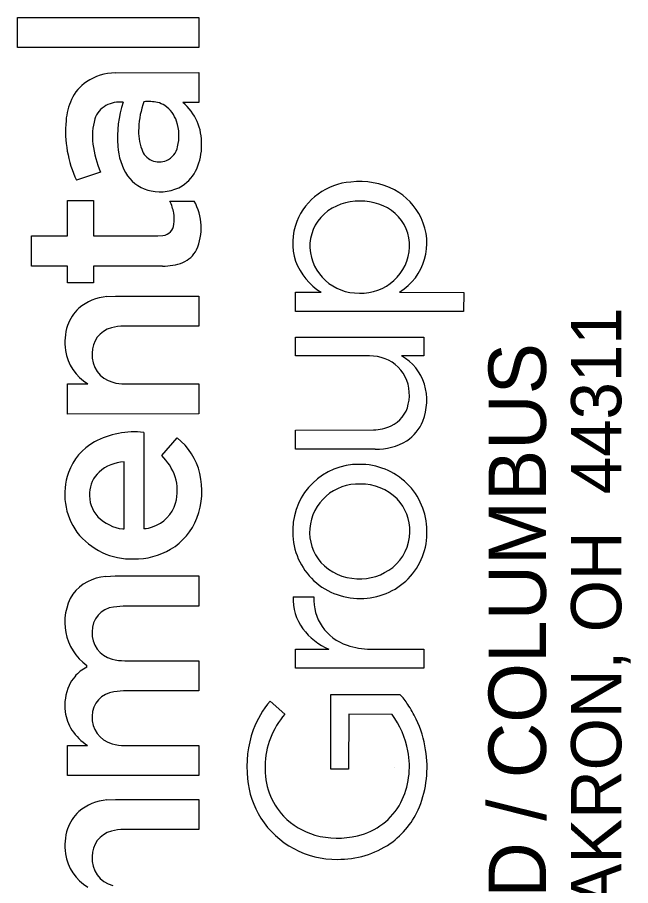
# Model space of a CAD drawing. Extents: x -1 to 34, y 0 to 22.
# Drawn here: x 32.376 to 32.984, y 3.882 to 4.744 of the extents above; entities that cross this region are included whole.
import ezdxf

# ---------------------------------------------------------------- set-up
doc = ezdxf.new("R2010")
doc.units = 0
doc.layers.add('SH_Data', color=7, linetype='Continuous')

msp = doc.modelspace()

# ---------------------------------------------------------------- linework, layer by layer
at = {"layer": 'SH_Data'}
for p, q in [((32.37557, 4.71411), (32.37557, 4.74397)), ((32.37557, 4.74397), (32.55571, 4.74397)), ((32.55571, 4.74397), (32.55571, 4.71411)), ((32.55571, 4.71411), (32.37557, 4.71411)), ((32.47265, 4.68899), (32.55553, 4.68918)), ((32.55553, 4.68918), (32.55571, 4.65956)), ((32.55571, 4.65956), (32.53971, 4.65956)), ((32.45818, 4.59045), (32.43431, 4.58233)), ((32.42542, 4.52705), (32.42548, 4.56209)), ((32.42548, 4.56209), (32.45108, 4.56209)), ((32.45108, 4.56209), (32.45117, 4.52705)), ((32.52695, 4.56159), (32.5511, 4.56159)), ((32.38964, 4.52701), (32.42542, 4.52705)), ((32.38964, 4.49719), (32.38964, 4.52701)), ((32.45117, 4.52705), (32.51498, 4.52705)), ((32.51498, 4.52705), (32.52005, 4.52749)), ((32.42542, 4.49717), (32.38964, 4.49719)), ((32.42542, 4.48067), (32.42542, 4.49717)), ((32.51969, 4.49718), (32.45108, 4.49715)), ((32.45108, 4.49715), (32.45108, 4.48066)), ((32.45108, 4.48066), (32.42542, 4.48067)), ((32.46439, 4.46686), (32.47289, 4.46732)), ((32.47289, 4.46732), (32.55571, 4.46732)), ((32.55571, 4.46732), (32.55571, 4.43753)), ((32.65152, 4.47113), (32.67709, 4.47115)), ((32.65152, 4.45215), (32.65152, 4.47113)), ((32.75491, 4.47132), (32.81858, 4.47108)), ((32.81858, 4.47108), (32.81843, 4.45215)), ((32.81843, 4.45215), (32.65152, 4.45215)), ((32.55571, 4.43753), (32.4814, 4.43746)), ((32.65152, 4.40801), (32.65153, 4.42672)), ((32.65153, 4.42672), (32.7791, 4.42664)), ((32.7791, 4.42664), (32.77908, 4.40796)), ((32.7249, 4.40796), (32.65152, 4.40801)), ((32.7328, 4.40727), (32.7249, 4.40796)), ((32.77908, 4.40796), (32.75689, 4.40796)), ((32.42542, 4.38016), (32.44552, 4.38021)), ((32.42542, 4.35035), (32.42542, 4.38016)), ((32.48222, 4.38021), (32.55569, 4.38021)), ((32.55569, 4.38021), (32.55571, 4.35045)), ((32.55571, 4.35045), (32.42542, 4.35035)), ((32.65154, 4.33443), (32.72905, 4.3345)), ((32.65165, 4.31543), (32.65154, 4.33443)), ((32.50108, 4.33209), (32.50118, 4.23657)), ((32.51882, 4.30927), (32.53422, 4.32662)), ((32.73073, 4.31543), (32.65165, 4.31543)), ((32.48144, 4.23644), (32.48144, 4.30296)), ((32.48016, 4.23628), (32.48144, 4.23644)), ((32.46329, 4.18915), (32.47259, 4.18968)), ((32.47259, 4.18968), (32.55557, 4.18968)), ((32.55557, 4.18968), (32.55571, 4.15982)), ((32.64932, 4.16907), (32.66978, 4.16907)), ((32.48058, 4.15981), (32.47102, 4.15881)), ((32.55571, 4.15982), (32.48058, 4.15981)), ((32.65152, 4.11699), (32.68476, 4.117)), ((32.65152, 4.098), (32.65152, 4.11699)), ((32.72605, 4.11703), (32.7791, 4.11696)), ((32.7791, 4.11696), (32.77903, 4.098)), ((32.48218, 4.10553), (32.55571, 4.10548)), ((32.55571, 4.10548), (32.55571, 4.07568)), ((32.44443, 4.09922), (32.44455, 4.10072)), ((32.77903, 4.098), (32.65152, 4.098)), ((32.4809, 4.07567), (32.47143, 4.07474)), ((32.55571, 4.07568), (32.4809, 4.07567)), ((32.6868, 4.07185), (32.75516, 4.07192)), ((32.6868, 3.99778), (32.6868, 4.07185)), ((32.62636, 4.06548), (32.64114, 4.05241)), ((32.70448, 4.05241), (32.70432, 3.99775)), ((32.74737, 4.05227), (32.70448, 4.05241)), ((32.42542, 3.99152), (32.42545, 4.02138)), ((32.42545, 4.02138), (32.44515, 4.02138)), ((32.48206, 4.02138), (32.55571, 4.02136)), ((32.55571, 4.02136), (32.55571, 3.99156)), ((32.75, 4), (32.75, 4)), ((32.55571, 3.99156), (32.42542, 3.99152)), ((32.70432, 3.99775), (32.6868, 3.99778)), ((32.46439, 3.96736), (32.47289, 3.96783)), ((32.47289, 3.96783), (32.55571, 3.96783)), ((32.55571, 3.96783), (32.55571, 3.93804)), ((32.55571, 3.93804), (32.4814, 3.93796))]:
    msp.add_line(p, q, dxfattribs=at)
msp.add_lwpolyline([(32.37557, 4.71411), (32.37557, 4.74397), (32.55571, 4.74397), (32.55571, 4.71411)], close=True, dxfattribs=at)
for points in [[(32.47265, 4.68899), (32.55553, 4.68918), (32.55571, 4.65956)], [(32.55571, 4.65956), (32.53971, 4.65956)], [(32.45818, 4.59045), (32.43431, 4.58233)], [(32.51969, 4.49718), (32.45108, 4.49715), (32.45108, 4.48066), (32.42542, 4.48067), (32.42542, 4.49717), (32.38964, 4.49719), (32.38964, 4.52701), (32.42542, 4.52705), (32.42548, 4.56209), (32.45108, 4.56209), (32.45117, 4.52705), (32.51498, 4.52705), (32.52005, 4.52749)], [(32.52695, 4.56159), (32.5511, 4.56159)], [(32.46439, 4.46686), (32.47289, 4.46732), (32.55571, 4.46732), (32.55571, 4.43753), (32.4814, 4.43746)], [(32.75491, 4.47132), (32.81858, 4.47108), (32.81843, 4.45215), (32.65152, 4.45215)], [(32.65152, 4.45215), (32.65152, 4.47113), (32.67709, 4.47115)], [(32.7328, 4.40727), (32.7249, 4.40796), (32.65152, 4.40801), (32.65153, 4.42672), (32.7791, 4.42664), (32.77908, 4.40796), (32.75689, 4.40796)], [(32.42542, 4.35035), (32.42542, 4.38016), (32.44552, 4.38021)], [(32.48222, 4.38021), (32.55569, 4.38021), (32.55571, 4.35045), (32.42542, 4.35035)], [(32.73073, 4.31543), (32.65165, 4.31543), (32.65154, 4.33443), (32.72905, 4.3345)], [(32.50108, 4.33209), (32.50118, 4.23657)], [(32.51882, 4.30927), (32.53422, 4.32662)], [(32.48016, 4.23628), (32.48144, 4.23644), (32.48144, 4.30296)], [(32.46329, 4.18915), (32.47259, 4.18968), (32.55557, 4.18968), (32.55571, 4.15982), (32.48058, 4.15981), (32.47102, 4.15881)], [(32.64932, 4.16907), (32.66978, 4.16907)], [(32.72605, 4.11703), (32.7791, 4.11696), (32.77903, 4.098), (32.65152, 4.098)], [(32.65152, 4.098), (32.65152, 4.11699), (32.68476, 4.117)], [(32.48218, 4.10553), (32.55571, 4.10548), (32.55571, 4.07568), (32.4809, 4.07567), (32.47143, 4.07474)], [(32.44443, 4.09922), (32.44455, 4.10072)], [(32.74737, 4.05227), (32.70448, 4.05241), (32.70432, 3.99775), (32.6868, 3.99778), (32.6868, 4.07185), (32.75516, 4.07192)], [(32.62636, 4.06548), (32.64114, 4.05241)], [(32.42542, 3.99152), (32.42545, 4.02138), (32.44515, 4.02138)], [(32.48206, 4.02138), (32.55571, 4.02136), (32.55571, 3.99156), (32.42542, 3.99152)], [(32.46439, 3.96736), (32.47289, 3.96783), (32.55571, 3.96783), (32.55571, 3.93804), (32.4814, 3.93796)]]:
    msp.add_lwpolyline(points, dxfattribs=at)
for centre, radius, start, end in [((32.47452, 4.63256), 0.05646, 91.89422, 122.63175), ((32.47452, 4.63256), 0.05646, 91.89422, 122.63175), ((32.46847, 4.64467), 0.04302, 124.53704, 155.65938), ((32.46847, 4.64467), 0.04302, 124.53704, 155.65938), ((32.48824, 4.63612), 0.06457, 155.9764, 175.31491), ((32.48824, 4.63612), 0.06457, 155.9764, 175.31491), ((32.47525, 4.6356), 0.024, 119.42515, 161.66285), ((32.47525, 4.6356), 0.024, 119.42515, 161.66285), ((32.47786, 4.62778), 0.03213, 85.38017, 116.62224), ((32.47786, 4.62778), 0.03213, 85.38017, 116.62224), ((32.58787, 4.62508), 0.1129, 162.08213, 184.52847), ((32.58787, 4.62508), 0.1129, 162.08213, 184.52847), ((32.58013, 4.63131), 0.08411, 159.83657, 178.03621), ((32.58013, 4.63131), 0.08411, 159.83657, 178.03621), ((32.50509, 4.60743), 0.05302, 79.66963, 94.23216), ((32.50509, 4.60743), 0.05302, 79.66963, 94.23216), ((32.50892, 4.63643), 0.02384, 56.89129, 76.21489), ((32.50892, 4.63643), 0.02384, 56.89129, 76.21489), ((32.5052, 4.63184), 0.02973, 17.59837, 55.72819), ((32.5052, 4.63184), 0.02973, 17.59837, 55.72819), ((32.50551, 4.61914), 0.05295, 358.07459, 49.76196), ((32.50551, 4.61914), 0.05295, 358.07459, 49.76196), ((32.53639, 4.63078), 0.113, 174.61011, 205.38987), ((32.53639, 4.63078), 0.113, 174.61011, 205.38987), ((32.50758, 4.62645), 0.05758, 163.13694, 188.16749), ((32.50758, 4.62645), 0.05758, 163.13694, 188.16749), ((32.4916, 4.6264), 0.04435, 345.94084, 18.99188), ((32.4916, 4.6264), 0.04435, 345.94084, 18.99188), ((32.54655, 4.6303), 0.05063, 175.59026, 199.88569), ((32.54655, 4.6303), 0.05063, 175.59026, 199.88569), ((32.54725, 4.62973), 0.09735, 186.75982, 203.79807), ((32.54725, 4.62973), 0.09735, 186.75982, 203.79807), ((32.53279, 4.61874), 0.05752, 182.56764, 213.71437), ((32.53279, 4.61874), 0.05752, 182.56764, 213.71437), ((32.51642, 4.61886), 0.01841, 198.28436, 293.30806), ((32.51642, 4.61886), 0.01841, 198.28436, 293.30806), ((32.51521, 4.61994), 0.01989, 295.28829, 347.46387), ((32.51521, 4.61994), 0.01989, 295.28829, 347.46387), ((32.50187, 4.61678), 0.05657, 336.01604, 0.59505), ((32.50187, 4.61678), 0.05657, 336.01604, 0.59505), ((32.51752, 4.60969), 0.03938, 303.44357, 336.18), ((32.51752, 4.60969), 0.03938, 303.44357, 336.18), ((32.51487, 4.60782), 0.03656, 215.06685, 259.81327), ((32.51487, 4.60782), 0.03656, 215.06685, 259.81327), ((32.51753, 4.6131), 0.04227, 257.52557, 300.88195), ((32.51753, 4.6131), 0.04227, 257.52557, 300.88195), ((32.71081, 4.51825), 0.06243, 93.98662, 158.31194), ((32.71081, 4.51825), 0.06243, 93.98662, 158.31194), ((32.71557, 4.5065), 0.07459, 62.68889, 97.01346), ((32.71557, 4.5065), 0.07459, 62.68889, 97.01346), ((32.72123, 4.51914), 0.06076, 25.06574, 61.96022), ((32.72123, 4.51914), 0.06076, 25.06574, 61.96022), ((32.48625, 4.54199), 0.04518, 10.15449, 25.72303), ((32.48625, 4.54199), 0.04518, 10.15449, 25.72303), ((32.50302, 4.53506), 0.05491, 336.58903, 28.89913), ((32.50302, 4.53506), 0.05491, 336.58903, 28.89913), ((32.71379, 4.51017), 0.05134, 87.89653, 131.18123), ((32.71379, 4.51017), 0.05134, 87.89653, 131.18123), ((32.7175, 4.51023), 0.05127, 49.90886, 92.03625), ((32.7175, 4.51023), 0.05127, 49.90886, 92.03625), ((32.49573, 4.54365), 0.03556, 351.91398, 10.20594), ((32.49573, 4.54365), 0.03556, 351.91398, 10.20594), ((32.70695, 4.52016), 0.05815, 158.65601, 198.17101), ((32.70695, 4.52016), 0.05815, 158.65601, 198.17101), ((32.7092, 4.51674), 0.04338, 132.32887, 182.09489), ((32.7092, 4.51674), 0.04338, 132.32887, 182.09489), ((32.72154, 4.51733), 0.04327, 358.04871, 47.94467), ((32.72154, 4.51733), 0.04327, 358.04871, 47.94467), ((32.7245, 4.52004), 0.05743, 301.97764, 25.64176), ((32.7245, 4.52004), 0.05743, 301.97764, 25.64176), ((32.51837, 4.54001), 0.01263, 277.61423, 353.79181), ((32.51837, 4.54001), 0.01263, 277.61423, 353.79181), ((32.71352, 4.51815), 0.04776, 183.59741, 271.7045), ((32.71352, 4.51815), 0.04776, 183.59741, 271.7045), ((32.71717, 4.51801), 0.04766, 267.31494, 357.4019), ((32.71717, 4.51801), 0.04766, 267.31494, 357.4019), ((32.52913, 4.52612), 0.02749, 292.68889, 332.05977), ((32.52913, 4.52612), 0.02749, 292.68889, 332.05977), ((32.52088, 4.54856), 0.05139, 268.67266, 291.52354), ((32.52088, 4.54856), 0.05139, 268.67266, 291.52354), ((32.7103, 4.52433), 0.0627, 200.83985, 238.01619), ((32.7103, 4.52433), 0.0627, 200.83985, 238.01619), ((32.46871, 4.41716), 0.04988, 94.97056, 130.22484), ((32.46871, 4.41716), 0.04988, 94.97056, 130.22484), ((32.46348, 4.42551), 0.04016, 132.22383, 161.68229), ((32.46348, 4.42551), 0.04016, 132.22383, 161.68229), ((32.47872, 4.42108), 0.05602, 162.27398, 187.79173), ((32.47872, 4.42108), 0.05602, 162.27398, 187.79173), ((32.48108, 4.39145), 0.04601, 89.60515, 105.33026), ((32.48108, 4.39145), 0.04601, 89.60515, 105.33026), ((32.47482, 4.41155), 0.02498, 103.68683, 182.21395), ((32.47482, 4.41155), 0.02498, 103.68683, 182.21395), ((32.47027, 4.4209), 0.04763, 188.96462, 238.69865), ((32.47027, 4.4209), 0.04763, 188.96462, 238.69865), ((32.47735, 4.40846), 0.02757, 175.58441, 255.13816), ((32.47735, 4.40846), 0.02757, 175.58441, 255.13816), ((32.72711, 4.36998), 0.03772, 33.50082, 81.32954), ((32.72711, 4.36998), 0.03772, 33.50082, 81.32954), ((32.73239, 4.36485), 0.04959, 17.62209, 60.38974), ((32.73239, 4.36485), 0.04959, 17.62209, 60.38974), ((32.72414, 4.3695), 0.04048, 346.56179, 31.75389), ((32.72414, 4.3695), 0.04048, 346.56179, 31.75389), ((32.48183, 4.42235), 0.04215, 254.08913, 270.52838), ((32.48183, 4.42235), 0.04215, 254.08913, 270.52838), ((32.72343, 4.36415), 0.05838, 339.16197, 15.61485), ((32.72343, 4.36415), 0.05838, 339.16197, 15.61485), ((32.73371, 4.36616), 0.03042, 294.63214, 348.48625), ((32.73371, 4.36616), 0.03042, 294.63214, 348.48625), ((32.739, 4.35901), 0.04201, 303.10391, 338.15613), ((32.739, 4.35901), 0.04201, 303.10391, 338.15613), ((32.72747, 4.38081), 0.04633, 271.95199, 294.08943), ((32.72747, 4.38081), 0.04633, 271.95199, 294.08943), ((32.49176, 4.24874), 0.08387, 83.62118, 118.28448), ((32.49176, 4.24874), 0.08387, 83.62118, 118.28448), ((32.49399, 4.2763), 0.06443, 13.53275, 51.36266), ((32.49399, 4.2763), 0.06443, 13.53275, 51.36266), ((32.47894, 4.27368), 0.05583, 118.82935, 160.62242), ((32.47894, 4.27368), 0.05583, 118.82935, 160.62242), ((32.7321, 4.37256), 0.05715, 268.62699, 301.47779), ((32.7321, 4.37256), 0.05715, 268.62699, 301.47779), ((32.48033, 4.27018), 0.05485, 19.0387, 45.44322), ((32.48033, 4.27018), 0.05485, 19.0387, 45.44322), ((32.4844, 4.26071), 0.04236, 94.01311, 130.88062), ((32.4844, 4.26071), 0.04236, 94.01311, 130.88062), ((32.71435, 4.23484), 0.06552, 89.48213, 178.77752), ((32.71435, 4.23484), 0.06552, 89.48213, 178.77752), ((32.71582, 4.23414), 0.06623, 0.42265, 90.7613), ((32.71582, 4.23414), 0.06623, 0.42265, 90.7613), ((32.48697, 4.27074), 0.06438, 160.52138, 215.78155), ((32.48697, 4.27074), 0.06438, 160.52138, 215.78155), ((32.47703, 4.2709), 0.02985, 132.98553, 177.1802), ((32.47703, 4.2709), 0.02985, 132.98553, 177.1802), ((32.48289, 4.27384), 0.0758, 339.35431, 13.37708), ((32.48289, 4.27384), 0.0758, 339.35431, 13.37708), ((32.48724, 4.27433), 0.04701, 344.60723, 17.00675), ((32.48724, 4.27433), 0.04701, 344.60723, 17.00675), ((32.71397, 4.23244), 0.04846, 87.68827, 175.01696), ((32.71397, 4.23244), 0.04846, 87.68827, 175.01696), ((32.71659, 4.23036), 0.05052, 44.91202, 90.75914), ((32.71659, 4.23036), 0.05052, 44.91202, 90.75914), ((32.47824, 4.26966), 0.03114, 175.00138, 223.2876), ((32.47824, 4.26966), 0.03114, 175.00138, 223.2876), ((32.71955, 4.23452), 0.04549, 358.32279, 43.83486), ((32.71955, 4.23452), 0.04549, 358.32279, 43.83486), ((32.49895, 4.27177), 0.03504, 288.01084, 343.55364), ((32.49895, 4.27177), 0.03504, 288.01084, 343.55364), ((32.48546, 4.27826), 0.04232, 225.06454, 262.79701), ((32.48546, 4.27826), 0.04232, 225.06454, 262.79701), ((32.49548, 4.26982), 0.0626, 300.94393, 338.73223), ((32.49548, 4.26982), 0.0626, 300.94393, 338.73223), ((32.48908, 4.27516), 0.06872, 217.74341, 271.65606), ((32.48908, 4.27516), 0.06872, 217.74341, 271.65606), ((32.50129, 4.25678), 0.02021, 269.70042, 294.87295), ((32.50129, 4.25678), 0.02021, 269.70042, 294.87295), ((32.71483, 4.2334), 0.06606, 177.53728, 270.94524), ((32.71483, 4.2334), 0.06606, 177.53728, 270.94524), ((32.71085, 4.23311), 0.0453, 175.51467, 221.42047), ((32.71085, 4.23311), 0.0453, 175.51467, 221.42047), ((32.71671, 4.23271), 0.06536, 269.30834, 1.67905), ((32.71671, 4.23271), 0.06536, 269.30834, 1.67905), ((32.71931, 4.23374), 0.04572, 308.90382, 359.30947), ((32.71931, 4.23374), 0.04572, 308.90382, 359.30947), ((32.49204, 4.27702), 0.07055, 269.20529, 300.33566), ((32.49204, 4.27702), 0.07055, 269.20529, 300.33566), ((32.71399, 4.23734), 0.05046, 222.66255, 268.37331), ((32.71399, 4.23734), 0.05046, 222.66255, 268.37331), ((32.71567, 4.23859), 0.05178, 266.55312, 308.67253), ((32.71567, 4.23859), 0.05178, 266.55312, 308.67253), ((32.46638, 4.14404), 0.04521, 93.91118, 142.30723), ((32.46638, 4.14404), 0.04521, 93.91118, 142.30723), ((32.47585, 4.14373), 0.05319, 148.28793, 233.9556), ((32.47585, 4.14373), 0.05319, 148.28793, 233.9556), ((32.69878, 4.16662), 0.04952, 177.16211, 216.28024), ((32.69878, 4.16662), 0.04952, 177.16211, 216.28024), ((32.71735, 4.16638), 0.04764, 176.76988, 252.15044), ((32.71735, 4.16638), 0.04764, 176.76988, 252.15044), ((32.47384, 4.13499), 0.02399, 96.75763, 181.6251), ((32.47384, 4.13499), 0.02399, 96.75763, 181.6251), ((32.70975, 4.17555), 0.06366, 216.91526, 246.88619), ((32.70975, 4.17555), 0.06366, 216.91526, 246.88619), ((32.47577, 4.13241), 0.02597, 175.81573, 256.16716), ((32.47577, 4.13241), 0.02597, 175.81573, 256.16716), ((32.7269, 4.19175), 0.07473, 251.13884, 269.34694), ((32.7269, 4.19175), 0.07473, 251.13884, 269.34694), ((32.4817, 4.15053), 0.04501, 254.34629, 270.61033), ((32.4817, 4.15053), 0.04501, 254.34629, 270.61033), ((32.4638, 4.06267), 0.04137, 117.91625, 139.24296), ((32.4638, 4.06267), 0.04137, 117.91625, 139.24296), ((32.46194, 4.06452), 0.03875, 139.52447, 154.84698), ((32.46194, 4.06452), 0.03875, 139.52447, 154.84698), ((32.47144, 4.0612), 0.04877, 156.06382, 187.3493), ((32.47144, 4.0612), 0.04877, 156.06382, 187.3493), ((32.47421, 4.05056), 0.02434, 96.5532, 179.94902), ((32.47421, 4.05056), 0.02434, 96.5532, 179.94902), ((32.72498, 4.03937), 0.04438, 30.98913, 47.16099), ((32.72498, 4.03937), 0.04438, 30.98913, 47.16099), ((32.70163, 4.00187), 0.09855, 139.79476, 159.13696), ((32.70163, 4.00187), 0.09855, 139.79476, 159.13696), ((32.67091, 4.00018), 0.11106, 25.30315, 33.96179), ((32.67091, 4.00018), 0.11106, 25.30315, 33.96179), ((32.46461, 4.05974), 0.04181, 186.5579, 213.38846), ((32.46461, 4.05974), 0.04181, 186.5579, 213.38846), ((32.47608, 4.04863), 0.02628, 175.722, 255.78627), ((32.47608, 4.04863), 0.02628, 175.722, 255.78627), ((32.69899, 4.00079), 0.07753, 138.25804, 179.70064), ((32.69899, 4.00079), 0.07753, 138.25804, 179.70064), ((32.67889, 4.00099), 0.08556, 10.07509, 36.83189), ((32.67889, 4.00099), 0.08556, 10.07509, 36.83189), ((32.6704, 3.99987), 0.11166, 8.80339, 25.33484), ((32.6704, 3.99987), 0.11166, 8.80339, 25.33484), ((32.47886, 4.07078), 0.0598, 214.70433, 235.68724), ((32.47886, 4.07078), 0.0598, 214.70433, 235.68724), ((32.7187, 3.99968), 0.11536, 161.14379, 185.62812), ((32.7187, 3.99968), 0.11536, 161.14379, 185.62812), ((32.48195, 4.06518), 0.0438, 253.66719, 270.14979), ((32.48195, 4.06518), 0.0438, 253.66719, 270.14979), ((32.68425, 4.00057), 0.08036, 333.46689, 11.03668), ((32.68425, 4.00057), 0.08036, 333.46689, 11.03668), ((32.67564, 3.99977), 0.10649, 338.28866, 9.28548), ((32.67564, 3.99977), 0.10649, 338.28866, 9.28548), ((32.68811, 3.99732), 0.06676, 176.66577, 223.6912), ((32.68811, 3.99732), 0.06676, 176.66577, 223.6912), ((32.69336, 3.99699), 0.08987, 185.50773, 212.01294), ((32.69336, 3.99699), 0.08987, 185.50773, 212.01294), ((32.46871, 3.91767), 0.04988, 94.97056, 130.22484), ((32.46871, 3.91767), 0.04988, 94.97056, 130.22484), ((32.69868, 3.99547), 0.0652, 282.88151, 331.81475), ((32.69868, 3.99547), 0.0652, 282.88151, 331.81475), ((32.46348, 3.92602), 0.04016, 132.22383, 161.68229), ((32.46348, 3.92602), 0.04016, 132.22383, 161.68229), ((32.69835, 3.99168), 0.08241, 305.03061, 337.67573), ((32.69835, 3.99168), 0.08241, 305.03061, 337.67573), ((32.69211, 3.99748), 0.08908, 212.70222, 270.71399), ((32.69211, 3.99748), 0.08908, 212.70222, 270.71399), ((32.69045, 4.00011), 0.07039, 224.02147, 253.88), ((32.69045, 4.00011), 0.07039, 224.02147, 253.88), ((32.47872, 3.92158), 0.05602, 162.27398, 187.79173), ((32.47872, 3.92158), 0.05602, 162.27398, 187.79173), ((32.48108, 3.89196), 0.04601, 89.60515, 105.33026), ((32.48108, 3.89196), 0.04601, 89.60515, 105.33026), ((32.47482, 3.91206), 0.02498, 103.68683, 182.21395), ((32.47482, 3.91206), 0.02498, 103.68683, 182.21395), ((32.69318, 4.01254), 0.08309, 254.45353, 283.9512), ((32.69318, 4.01254), 0.08309, 254.45353, 283.9512), ((32.69429, 3.99979), 0.09138, 269.3273, 304.19632), ((32.69429, 3.99979), 0.09138, 269.3273, 304.19632), ((32.47027, 3.92141), 0.04763, 188.96462, 238.69865), ((32.47027, 3.92141), 0.04763, 188.96462, 238.69865), ((32.47735, 3.90897), 0.02757, 175.58441, 255.13816), ((32.47735, 3.90897), 0.02757, 175.58441, 255.13816)]:
    msp.add_arc(centre, radius, start, end, dxfattribs=at)

# ---------------------------------------------------------------- texts
for s, height, p in [('450 GRANT ST., AKRON, OH  44311', 0.0498462, (32.97489, 3.33738)), ('AKRON / CLEVELAND / COLUMBUS', 0.056969, (32.90012, 3.138))]:
    msp.add_text(s, height=height, rotation=90, dxfattribs=at).set_placement(p)

doc.saveas('drawing.dxf')
